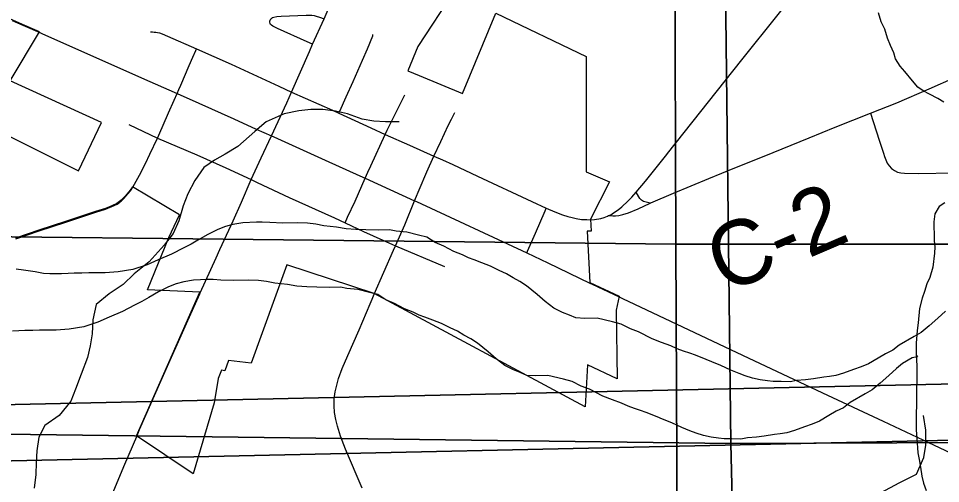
# Model space of a CAD drawing. Extents: x -21.1 to 50.3, y -4.9 to 22.1.
# Drawn here: x 5.889 to 6.702, y 17.924 to 18.334 of the extents above; entities that cross this region are included whole.
import ezdxf

# ---------------------------------------------------------------- set-up
doc = ezdxf.new("R2010")
doc.units = 0
for name, color, linetype in [('GM_X_City_Street', 7, 'Continuous'), ('GM_X_Corporation', 7, 'Continuous'), ('GM_X_County_Road', 7, 'Continuous'), ('GM_X_County_Road_Text', 7, 'Continuous'), ('GM_X_Minor_River', 7, 'Continuous'), ('GM_X_Section', 7, 'Continuous'), ('GM_X_State_Route', 7, 'Continuous'), ('GM_X_Township_Road', 7, 'Continuous'), ('GM_X_US_Route', 7, 'Continuous')]:
    doc.layers.add(name, color=color, linetype=linetype)

msp = doc.modelspace()

# ---------------------------------------------------------------- linework, layer by layer
at = {"layer": 'GM_X_City_Street'}
for points in [[(6.14825, 18.31087), (6.14333, 18.31307), (6.11735, 18.32471), (6.11323, 18.32686), (6.11186, 18.32766), (6.1112, 18.32837), (6.11082, 18.32904), (6.11045, 18.33036), (6.11054, 18.33126), (6.11073, 18.33211), (6.11146, 18.33328), (6.11226, 18.33393), (6.11276, 18.33433), (6.11413, 18.33482), (6.11683, 18.33538), (6.12042, 18.33565), (6.14255, 18.33651), (6.14503, 18.33655), (6.14759, 18.33645), (6.14967, 18.33612), (6.15147, 18.33565), (6.15435, 18.33465), (6.15828, 18.3333)], [(6.00548, 18.32173), (6.00724, 18.32173), (6.00862, 18.32164), (6.01022, 18.32147), (6.01168, 18.32126), (6.0134, 18.32082), (6.01556, 18.32009), (6.02028, 18.3181), (6.04604, 18.30677), (6.07658, 18.29333), (6.11848, 18.27398), (6.12406, 18.2714), (6.12965, 18.26877)], [(6.17132, 18.25014), (6.17209, 18.25186), (6.17783, 18.26463), (6.18398, 18.27807), (6.19213, 18.29671), (6.19658, 18.30678), (6.20115, 18.31823), (6.20139, 18.31938)], [(6.02876, 18.26742), (6.03045, 18.27096), (6.03222, 18.27492), (6.03943, 18.29217), (6.04258, 18.29956), (6.04535, 18.30535), (6.04604, 18.30677)], [(6.12965, 18.26877), (6.1657, 18.25272), (6.17132, 18.25014), (6.19954, 18.23716), (6.21224, 18.23148), (6.23366, 18.22189), (6.25514, 18.21213)], [(6.19444, 18.1928), (6.19693, 18.19805), (6.19955, 18.20379), (6.21224, 18.23148), (6.214, 18.2353), (6.22943, 18.26638)], [(6.25514, 18.21213), (6.26106, 18.22504), (6.26766, 18.2393), (6.27058, 18.24495), (6.27365, 18.25062)], [(5.98624, 18.24014), (6.01155, 18.22826), (6.04612, 18.21338), (6.07187, 18.20192), (6.09398, 18.19166)], [(6.09398, 18.19166), (6.09935, 18.18903), (6.12765, 18.17584), (6.16747, 18.15787), (6.17677, 18.15354), (6.19294, 18.14601), (6.21849, 18.13433), (6.22128, 18.13316), (6.26457, 18.11508)], [(6.17677, 18.15354), (6.17906, 18.15846), (6.18568, 18.17276), (6.19444, 18.1928)], [(6.22128, 18.13316), (6.22956, 18.15188), (6.23791, 18.17304)]]:
    msp.add_lwpolyline(points, dxfattribs=at)
at = {"layer": 'GM_X_Corporation'}
for points in [[(6.27291, 18.35797), (6.24102, 18.30888), (6.23214, 18.28746), (6.24205, 18.28335), (6.2803, 18.26749), (6.30958, 18.33812), (6.38923, 18.30009), (6.38919, 18.19835), (6.40995, 18.18953), (6.39319, 18.15686), (6.39373, 18.14621), (6.39019, 18.14621), (6.39237, 18.10106), (6.41827, 18.08886), (6.41561, 18.07669), (6.41655, 18.01612), (6.39029, 18.02843), (6.38839, 17.99145), (6.20234, 18.09124), (6.1256, 18.11663), (6.09397, 18.02982), (6.07423, 18.03225), (6.07089, 18.02308), (6.06786, 18.02384), (6.06486, 18.01643), (6.06159, 17.99506), (6.0429, 17.93247), (5.993, 17.96582), (6.04896, 18.09242), (6.0028, 18.09443), (6.02163, 18.14048), (6.03089, 18.16068), (5.98941, 18.18515), (5.98748, 18.18221), (5.98346, 18.17747), (5.98169, 18.1756), (5.97968, 18.17358), (5.97802, 18.17223), (5.97566, 18.17057), (5.97117, 18.16838), (5.96562, 18.16626), (5.95689, 18.16351), (5.94823, 18.16059), (5.93055, 18.15481), (5.90709, 18.14713), (5.88646, 18.13992)], [(5.87484, 18.23272), (5.94196, 18.19922), (5.96235, 18.24191), (5.88176, 18.27864), (5.9076, 18.32179), (5.89264, 18.32829), (5.88158, 18.33324)]]:
    msp.add_lwpolyline(points, dxfattribs=at)
at = {"layer": 'GM_X_County_Road'}
for points in [[(6.63968, 18.25009), (6.66303, 18.25933), (6.69153, 18.27155), (6.71423, 18.28163), (6.757, 18.30013), (6.80279, 18.31948), (6.81999, 18.32663), (6.8486, 18.33872), (6.88295, 18.35317), (6.90578, 18.36293), (6.9228, 18.37051), (6.97384, 18.39325), (7.01069, 18.40976), (7.04193, 18.42358), (7.06465, 18.43358), (7.07317, 18.43726), (7.09306, 18.44591), (7.11896, 18.45621), (7.15361, 18.46927)], [(6.44553, 18.17073), (6.44631, 18.17108), (6.46607, 18.17976), (6.49742, 18.19271), (6.5203, 18.20192), (6.54596, 18.21229), (6.58582, 18.22854), (6.60867, 18.23771), (6.63968, 18.25009)], [(6.44553, 18.17073), (6.44333, 18.17137), (6.43991, 18.17237), (6.43801, 18.17343), (6.43648, 18.17494), (6.43362, 18.17995), (6.43321, 18.18065)], [(6.40907, 18.15986), (6.41282, 18.1597), (6.41513, 18.1596), (6.41815, 18.15999), (6.42161, 18.16094), (6.42644, 18.16245), (6.43503, 18.166), (6.44553, 18.17073)]]:
    msp.add_lwpolyline(points, dxfattribs=at)
at = {"layer": 'GM_X_Minor_River'}
for points in [[(6.70442, 18.25978), (6.69907, 18.26317), (6.69182, 18.26693), (6.68609, 18.26993), (6.68151, 18.27295), (6.67691, 18.27862), (6.67001, 18.28694), (6.6658, 18.29147), (6.66195, 18.29791), (6.6604, 18.30322), (6.65732, 18.30966), (6.65462, 18.31611), (6.65229, 18.32407), (6.64921, 18.33051), (6.64688, 18.33848)], [(6.22445, 18.24248), (6.21232, 18.24248), (6.20208, 18.24324), (6.19185, 18.24476), (6.17896, 18.24969), (6.16835, 18.25196), (6.15736, 18.25347), (6.14674, 18.25347), (6.13613, 18.25233), (6.12324, 18.24968), (6.10731, 18.24247), (6.09745, 18.23413), (6.08228, 18.22085), (6.07129, 18.21402), (6.0618, 18.20871), (6.05232, 18.20226), (6.04436, 18.19088), (6.03829, 18.17912), (6.03411, 18.16851), (6.03031, 18.15523), (6.02538, 18.14423), (6.01741, 18.13399), (6.00414, 18.1192), (5.99086, 18.10858), (5.98138, 18.09909), (5.96887, 18.09113), (5.95749, 18.08164), (5.95445, 18.06799), (5.95406, 18.05585), (5.95216, 18.04523), (5.94988, 18.03499), (5.94419, 18.0202), (5.93925, 18.00693), (5.93508, 17.99631), (5.92483, 17.98379), (5.91232, 17.97507), (5.90701, 17.96483), (5.90511, 17.95269), (5.90472, 17.94245), (5.90434, 17.93183), (5.90281, 17.91969)], [(6.70529, 18.17127), (6.70037, 18.16782), (6.6966, 18.16134), (6.69549, 18.1545), (6.69552, 18.14956), (6.69593, 18.14425), (6.69596, 18.13779), (6.69638, 18.13247), (6.69603, 18.12677), (6.69457, 18.11461), (6.69196, 18.10548), (6.68933, 18.09976), (6.68746, 18.09292), (6.68521, 18.0872), (6.68298, 18.07808), (6.68191, 18.06553), (6.6808, 18.05869), (6.6801, 18.04767), (6.68015, 18.03855), (6.6806, 18.02716), (6.68067, 18.01424), (6.68032, 18.00778), (6.68041, 17.99183), (6.68006, 17.98689), (6.6801, 17.98043), (6.68015, 17.97131), (6.68057, 17.96372), (6.6814, 17.95081), (6.68258, 17.94511), (6.68376, 17.93828), (6.68495, 17.93031), (6.6865, 17.92424), (6.68882, 17.9178)], [(6.70601, 18.07568), (6.69919, 18.06956), (6.69161, 18.06268), (6.68441, 18.05695), (6.67834, 18.05349), (6.66506, 18.04582), (6.65938, 18.04123), (6.65293, 18.03816), (6.64648, 18.03432), (6.63813, 18.02934), (6.63167, 18.02665), (6.62484, 18.02433), (6.6161, 18.02124), (6.60926, 18.01892), (6.60355, 18.01813), (6.59861, 18.01773), (6.58948, 18.01616), (6.58263, 18.01536), (6.57465, 18.01455), (6.56894, 18.01338), (6.56095, 18.01372), (6.5541, 18.01368), (6.54914, 18.01442), (6.54267, 18.01514), (6.53581, 18.01662), (6.52933, 18.01887), (6.52398, 18.02073), (6.51674, 18.02373), (6.50796, 18.02787), (6.49995, 18.03124), (6.49499, 18.03311), (6.48545, 18.03686), (6.48049, 18.03873), (6.47515, 18.0406), (6.46943, 18.04247), (6.46371, 18.0451), (6.4557, 18.04809), (6.4473, 18.05146), (6.43547, 18.05748), (6.42822, 18.0601), (6.42021, 18.06423), (6.41258, 18.06647), (6.39886, 18.06943), (6.3882, 18.06938), (6.38021, 18.06971), (6.37448, 18.07234), (6.36838, 18.07458), (6.36075, 18.07834), (6.3531, 18.08438), (6.34622, 18.09042), (6.33665, 18.09796), (6.33093, 18.10173), (6.32482, 18.10511), (6.31909, 18.1085), (6.3126, 18.11151), (6.30497, 18.11526), (6.29734, 18.11826), (6.29047, 18.12088), (6.28551, 18.12275), (6.28017, 18.12538), (6.27254, 18.12838), (6.26376, 18.13289), (6.25613, 18.13627), (6.24887, 18.14078), (6.24162, 18.14264), (6.23133, 18.14525), (6.22181, 18.14633), (6.2161, 18.14744), (6.2062, 18.14701), (6.19516, 18.14733), (6.1864, 18.14766), (6.17765, 18.14837), (6.16926, 18.14984), (6.15822, 18.15092), (6.15098, 18.1524), (6.14374, 18.15312), (6.1346, 18.15345), (6.12204, 18.15338), (6.11062, 18.1537), (6.10377, 18.15404), (6.09882, 18.15402), (6.08664, 18.15357), (6.0779, 18.152), (6.07143, 18.15045), (6.0646, 18.14775), (6.05587, 18.14314), (6.04714, 18.13816), (6.04107, 18.1347), (6.03462, 18.13163), (6.02399, 18.12587), (6.01222, 18.12087), (6.00235, 18.11663), (5.98981, 18.11239), (5.97688, 18.11042), (5.96546, 18.10959), (5.951, 18.10952), (5.94491, 18.1091)], [(5.94491, 18.1091), (5.93806, 18.10906), (5.93273, 18.10903), (5.92702, 18.10862), (5.91675, 18.10857), (5.91103, 18.10891), (5.90379, 18.1104), (5.89351, 18.11186), (5.88703, 18.11258)], [(6.68022, 18.03681), (6.68131, 18.03552), (6.67637, 18.03473), (6.66802, 18.02975), (6.66272, 18.02516), (6.6559, 18.01905), (6.64833, 18.01217), (6.64113, 18.00643), (6.63505, 18.00298), (6.62177, 17.99531), (6.61609, 17.99072), (6.60964, 17.98764), (6.60319, 17.98381), (6.59484, 17.97882), (6.58838, 17.97613), (6.58155, 17.97381), (6.57281, 17.97072), (6.56597, 17.96841), (6.56027, 17.96762), (6.55532, 17.96721), (6.54619, 17.96564), (6.53935, 17.96484), (6.53136, 17.96404), (6.52565, 17.96287), (6.51766, 17.9632), (6.51081, 17.96317), (6.50585, 17.9639), (6.49938, 17.96462), (6.49252, 17.96611), (6.48604, 17.96835), (6.4807, 17.97022), (6.47345, 17.97322), (6.46467, 17.97735), (6.45666, 17.98072), (6.4517, 17.9826), (6.44216, 17.98634), (6.4372, 17.98821), (6.43186, 17.99008), (6.42614, 17.99195), (6.42042, 17.99458), (6.41241, 17.99758), (6.40401, 18.00095), (6.39218, 18.00696), (6.38493, 18.00958), (6.37692, 18.01372), (6.36929, 18.01595), (6.35557, 18.01892), (6.34492, 18.01886), (6.33692, 18.01919), (6.33119, 18.02182), (6.32509, 18.02407), (6.31746, 18.02782), (6.30981, 18.03386), (6.30293, 18.0399), (6.29337, 18.04744), (6.28764, 18.05121), (6.28153, 18.0546), (6.2758, 18.05798), (6.26931, 18.06099), (6.26168, 18.06475), (6.25405, 18.06774), (6.24718, 18.07036), (6.24222, 18.07224), (6.23688, 18.07487), (6.22925, 18.07786), (6.22047, 18.08237), (6.21284, 18.08575), (6.20558, 18.09027), (6.19834, 18.09213), (6.18804, 18.09473), (6.17852, 18.09582), (6.17281, 18.09693), (6.16291, 18.09649), (6.15187, 18.09681), (6.14312, 18.09714), (6.13436, 18.09785), (6.12597, 18.09933), (6.11493, 18.10041), (6.10769, 18.10189), (6.10045, 18.10261), (6.09131, 18.10293), (6.07875, 18.10287), (6.06733, 18.10318), (6.06048, 18.10353), (6.05553, 18.1035), (6.04335, 18.10305), (6.03461, 18.10148), (6.02814, 18.09993), (6.02131, 18.09723), (6.01258, 18.09263), (6.00385, 18.08764), (5.99778, 18.08419), (5.99133, 18.08111), (5.9807, 18.07536), (5.96893, 18.07035), (5.95906, 18.06612), (5.94652, 18.06187), (5.93359, 18.0599), (5.92217, 18.05908), (5.90771, 18.059), (5.90162, 18.05859)], [(5.90162, 18.05859), (5.89477, 18.05855), (5.88944, 18.05852), (5.88373, 18.05811)], [(6.6492, 17.91598), (6.6649, 17.92448), (6.68022, 17.93222), (6.6869, 17.94694), (6.68859, 17.95755), (6.68841, 17.97085), (6.68634, 17.9838)]]:
    msp.add_lwpolyline(points, dxfattribs=at)
at = {"layer": 'GM_X_Section'}
for points in [[(5.46172, 19.1492), (6.46467, 19.14528), (6.46827, 18.13471), (5.45742, 18.14589)], [(6.46467, 19.14528), (7.45853, 19.14217), (7.46215, 18.13462), (6.46827, 18.13471)], [(6.83581, 19.01172), (6.83569, 18.01448), (5.81893, 17.99203), (5.82494, 19.00715), (5.8818, 19.00728)], [(6.50457, 18.98884), (6.51666, 17.95921), (5.48815, 17.97251), (5.47114, 18.99721)], [(7.5274, 18.98311), (7.54061, 17.96333), (6.51666, 17.95921), (6.50457, 18.98884)], [(6.79252, 18.9612), (6.7924, 17.96396), (5.77564, 17.94152), (5.78166, 18.95663), (5.83851, 18.95676)], [(5.45742, 18.14589), (6.46827, 18.13471), (6.47301, 17.12604), (6.41542, 17.12601), (5.45266, 17.13084)], [(6.46827, 18.13471), (7.46215, 18.13462), (7.47526, 17.13233), (7.40705, 17.13199), (6.47301, 17.12604)], [(5.81893, 17.99203), (6.83569, 18.01448), (6.84408, 16.99761), (5.83147, 16.97938)], [(5.48815, 17.97251), (6.51666, 17.95921), (6.54146, 16.94121), (5.52017, 16.94387)], [(5.77564, 17.94152), (6.7924, 17.96396), (6.8008, 16.94709), (5.78818, 16.92886)], [(7.54061, 17.96333), (7.56617, 16.93816), (6.54146, 16.94121), (6.51666, 17.95921)]]:
    msp.add_lwpolyline(points, close=True, dxfattribs=at)
at = {"layer": 'GM_X_State_Route'}
for p, q in [((6.11213, 18.23021), (6.11398, 18.22937)), ((6.19444, 18.1928), (6.23791, 18.17304))]:
    msp.add_line(p, q, dxfattribs=at)
for points in [[(6.46026, 18.21378), (6.46089, 18.21456), (6.52646, 18.2972), (6.5903, 18.37724), (6.63115, 18.4281), (6.64196, 18.44303), (6.64623, 18.4501), (6.6498, 18.45635), (6.65299, 18.46275), (6.65637, 18.47034), (6.66162, 18.48504), (6.66562, 18.49982), (6.66991, 18.52081), (6.68561, 18.616), (6.70299, 18.72018), (6.70755, 18.74782), (6.71025, 18.75988)], [(6.11213, 18.23021), (6.12546, 18.25926), (6.12965, 18.26877), (6.14534, 18.30437), (6.14825, 18.31087), (6.15828, 18.3333), (6.16501, 18.34835), (6.16678, 18.35229)], [(6.06318, 18.1228), (6.06647, 18.13008), (6.07809, 18.15517), (6.08545, 18.17165), (6.09398, 18.19166), (6.10283, 18.2107), (6.11213, 18.23021)], [(6.11398, 18.22937), (6.15917, 18.20875), (6.18997, 18.19484), (6.19444, 18.1928)], [(6.24889, 18.19833), (6.25514, 18.21213), (6.26268, 18.20889), (6.27189, 18.20478), (6.29353, 18.19466)], [(6.3934, 18.15631), (6.39652, 18.15649), (6.40219, 18.15739), (6.40507, 18.15832), (6.40795, 18.15933), (6.40907, 18.15986), (6.4109, 18.16073), (6.41334, 18.16223), (6.41737, 18.16507), (6.42068, 18.16777), (6.42607, 18.17269), (6.42945, 18.17629), (6.43321, 18.18065), (6.44147, 18.19023), (6.46026, 18.21378)], [(6.23791, 18.17304), (6.24806, 18.19649), (6.24889, 18.19833)], [(6.29353, 18.19466), (6.34134, 18.17232), (6.35399, 18.16653), (6.36164, 18.16326), (6.36851, 18.16067), (6.37304, 18.15919), (6.37704, 18.15811), (6.38055, 18.15728), (6.38526, 18.1566), (6.38976, 18.15635), (6.3934, 18.15631)], [(6.04876, 18.09098), (6.04916, 18.09187), (6.06318, 18.1228)], [(6.01449, 18.01405), (6.01571, 18.01683), (6.0371, 18.06499), (6.04876, 18.09098)], [(5.99321, 17.96528), (5.99573, 17.97146), (6.01449, 18.01405)], [(5.88652, 17.8336), (5.90735, 17.85202), (5.94265, 17.88263), (5.95665, 17.89505), (5.96051, 17.89886), (5.96325, 17.90201), (5.96579, 17.90509), (5.9677, 17.90769), (5.96822, 17.90839), (5.97014, 17.91153), (5.97114, 17.91345), (5.97313, 17.91783), (5.98282, 17.94084), (5.99321, 17.96528)]]:
    msp.add_lwpolyline(points, dxfattribs=at)
at = {"layer": 'GM_X_Township_Road'}
for points in [[(6.01155, 18.22826), (6.01265, 18.23066), (6.02126, 18.2504), (6.02622, 18.26166), (6.02876, 18.26742)], [(6.63968, 18.25009), (6.64756, 18.22647), (6.65111, 18.21482), (6.65208, 18.21189), (6.6546, 18.20624), (6.65623, 18.20363), (6.6583, 18.20133), (6.66079, 18.19952), (6.66359, 18.19824), (6.66658, 18.19748), (6.66966, 18.19715), (6.68206, 18.19708), (6.713, 18.19768), (6.72846, 18.19815), (6.73775, 18.19815), (6.74084, 18.1981)], [(5.98994, 18.1851), (5.99582, 18.19565), (6.0009, 18.20595), (6.00492, 18.21404), (6.01155, 18.22826)], [(5.97906, 18.17236), (5.97989, 18.17304), (5.98189, 18.17505), (5.98367, 18.17693), (5.98769, 18.18167), (5.98994, 18.1851)], [(5.88667, 18.13938), (5.9073, 18.14658), (5.93076, 18.15426), (5.94844, 18.16004), (5.9571, 18.16296), (5.96583, 18.16572), (5.97137, 18.16783), (5.97587, 18.17002), (5.97823, 18.17168), (5.97906, 18.17236)], [(6.33683, 18.12706), (6.33745, 18.12847), (6.34448, 18.14438), (6.35304, 18.16398), (6.35399, 18.16653)], [(6.20255, 18.09069), (6.21959, 18.12946), (6.22128, 18.13316)], [(6.19182, 17.91979), (6.17729, 17.9541), (6.17286, 17.96564), (6.17008, 17.97447), (6.16858, 17.98042), (6.16755, 17.9864), (6.16716, 17.99247), (6.16729, 17.99855), (6.16814, 18.00462), (6.16943, 18.01059), (6.17115, 18.01648), (6.17423, 18.02519), (6.17912, 18.03655), (6.18917, 18.05927), (6.19898, 18.08209), (6.20076, 18.08639), (6.20255, 18.09069)]]:
    msp.add_lwpolyline(points, dxfattribs=at)
at = {"layer": 'GM_X_US_Route'}
for p, q in [((6.11213, 18.23021), (6.11398, 18.22937)), ((6.19444, 18.1928), (6.23791, 18.17304)), ((6.23791, 18.17304), (6.23973, 18.1722))]:
    msp.add_line(p, q, dxfattribs=at)
for points in [[(5.88363, 18.33187), (5.89285, 18.32774), (5.90781, 18.32124), (5.90962, 18.32043)], [(5.90962, 18.32043), (5.99734, 18.2813), (6.02876, 18.26742), (6.04797, 18.25895), (6.07883, 18.24513), (6.09845, 18.23616), (6.11213, 18.23021)], [(6.11398, 18.22937), (6.15917, 18.20875), (6.18997, 18.19484), (6.19444, 18.1928)], [(6.23973, 18.1722), (6.33683, 18.12706), (6.35562, 18.11819), (6.39258, 18.10052), (6.39443, 18.09964)], [(6.39443, 18.09964), (6.41847, 18.08831), (6.42119, 18.08703)], [(6.42119, 18.08703), (6.52705, 18.03708), (6.5974, 18.00391), (6.65083, 17.97888), (6.69589, 17.9576), (6.83344, 17.89297), (6.91234, 17.85587), (7.03858, 17.79596), (7.11094, 17.75966), (7.16049, 17.73364)]]:
    msp.add_lwpolyline(points, dxfattribs=at)

# ---------------------------------------------------------------- texts
at = {"layer": 'GM_X_County_Road_Text'}
msp.add_text('C-2', height=0.056818, rotation=23.14, dxfattribs=at).set_placement((6.51119, 18.09059))

doc.saveas('drawing.dxf')
